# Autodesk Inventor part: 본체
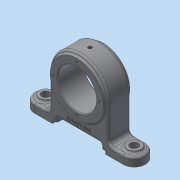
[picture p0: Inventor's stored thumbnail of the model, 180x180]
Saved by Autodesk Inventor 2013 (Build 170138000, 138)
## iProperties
Created: 2019-05
Part Number: 본체
Material: 일반
Document SubType Name: Modeling
Designer: dgall
Density: 1 g/cm^3
Author: dgall
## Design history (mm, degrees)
sketch "스케치1"
  geometry: L1 (0, 0)-(0, 60); C1 r 40 at (0, 60)
  constraints: 2 end point, 1 centre point, 1 coincident, 1 vertical
  dimensions: "d0" = 60 distance of L1.start L1.end; "d1" = 80 diameter of C1
extrude "돌출1" new body sketch "스케치1" stored distance "d2" = 30; taper "d3" = 0 deg
sketch "스케치2"
  geometry: L1 (0, -40)-(60, -40); L2 (0, 40)-(60, 40); L3 (60, 40)-(60, -40); L4 (60, 0)-(60, 75); L5 (60, 75)-(48, 75); L6 (48, 75)-(48, 40); L7 (60, 0)-(60, -75); L8 (60, -75)-(48, -75); L9 (48, -75)-(48, -40); A1 r 40 centre (0, 0) between (0, -40) and (0, 40) reference
  constraints: 18 end point, 4 perpendicular, 2 parallel, 2 point on circle, 2 point on line, 2 tangent, 1 collinear, 1 horizontal
  dimensions: "d4" = 60 distance of L1.start L1.end; "d5" = 60 distance of L2.start L2.end; "d6" = 75 distance of L4.start L4.end; "d7" = 12 distance of L4.end L5.end; "d8" = 75 distance of L4.start L7.end; "d9" = 12 distance of L7.end L8.end
extrude "돌출2" join sketch "스케치2" distance "d10" = 30; taper "d11" = 0 deg
fillet "모깎기1" dims "d12" = 15
fillet "모깎기2" dims "d13" = 15
sketch "스케치3"
  geometry: C1 r 9 at (15, -20); A1 r 15 centre (15, -20) between (0, -20) and (30, -20) reference; 1 further point
  constraints: 1 centre point, 1 coincident
  dimensions: "d14" = 18 diameter of C1
extrude "돌출3" join sketch "스케치3" distance "d16" = 3; taper "d17" = 0 deg
sketch "스케치4"
  geometry: C1 r 9 at (15, 20); A1 r 15 centre (15, 20) between (30, 20) and (0, 20) reference; 1 further point
  constraints: 1 centre point, 1 coincident
  dimensions: "d18" = 18 diameter of C1
extrude "돌출4" join sketch "스케치4" distance "d20" = 3; taper "d21" = 0 deg
fillet "모깎기3" dims "d22" = 3
fillet "모깎기4" dims "d23" = 3
fillet "모깎기5" dims "d24" = 6
fillet "모깎기6" dims "d25" = 3
sketch "스케치5"
  geometry: C1 r 9 at (0, 0) reference; C2 r 9 at (0, 120) reference; 1 further point
hole "구멍1" sketch "스케치5" at (0, 0), (0, 120) diameter "d26" = 11; stored, may be unused: countersink angle "d30" = 90 deg, drill point angle "d32" = 0 deg; dims "d27" = 6, "d28" = 4, "d29" = 2, "d31" = 20
sketch "스케치6"
  geometry: L1 (0, -60)-(0, 60) reference; L2 (0, 0)-(0, -36); L3 (0, -36)-(-4, -36); L4 (0, 0)-(0, 36); L5 (0, 36)-(-4, 36); L6 (0, 0)-(-10, 0); L7 (-10, 0)-(-10, -30); L8 (-10, -30)-(-4, -30); L9 (-4, -30)-(-4, -36); L10 (-10, 0)-(-10, 30); L11 (-10, 30)-(-4, 30); L12 (-4, 30)-(-4, 36)
  constraints: 22 end point, 4 perpendicular, 3 parallel, 2 point on line
  dimensions: "d33" = 36 distance of L2.start L2.end; "d34" = 4 distance of L2.end L3.end; "d35" = 36 distance of L2.start L4.end; "d36" = 4 distance of L4.end L5.end; "d37" = 10 distance of L2.start L6.end; "d38" = 30 distance of L6.end L7.end; "d39" = 6 distance of L7.end L8.end; "d40" = 30 distance of L6.end L10.end; "d41" = 6 distance of L10.end L11.end
extrude "돌출5" cut sketch "스케치6" stored distance "d42" = 3; taper "d43" = 0 deg
fillet "모깎기7" dims "d44" = 3
fillet "모깎기8" dims "d45" = 3
node "작업 평면1"
sketch "스케치7"
  geometry: L1 (-4, -33)-(-7, -33) reference; L2 (-4, -33)-(-4, -36) reference; L3 (-4, -36)-(0, -36) reference; L4 (0, -36)-(0, -60) reference; L5 (-9, -60)-(0, -60) reference; L6 (-9, -46)-(-9, -60) reference; L7 (-60, -37)-(-18, -37) reference; L8 (-18, 37)-(-60, 37) reference; L9 (-9, 60)-(-9, 46) reference; L10 (0, 60)-(-9, 60) reference; L11 (0, 60)-(0, 36) reference; L12 (0, 36)-(-4, 36) reference; L13 (-4, 36)-(-4, 33) reference; L14 (-7, 33)-(-4, 33) reference; L15 (-13, -27)-(-13, 27) reference; L16 (-18, 37)-(-60, 37) reference; L17 (-18, -40)-(-60, -40) reference; C1 r 36 at (-60, 0); A1 r 9 centre (-18, -46) between (-9, -46) and (-9.719, -42.474) reference; A2 r 37 centre (-60, 0) between (-60, 37) and (-60, -37) reference; A3 r 9 centre (-18, 46) between (-9.719, 42.474) and (-9, 46) reference; A4 r 6 centre (-7, 27) between (-7, 33) and (-13, 27) reference; A5 r 6 centre (-7, -27) between (-13, -27) and (-7, -33) reference; A6 r 40 centre (-60, 0) between (-60, 40) and (-60, -40) reference; 1 further point
  constraints: 1 centre point, 1 coincident, 2 other
  dimensions: "d46" = 72 diameter of C1
extrude "돌출6" join sketch "스케치7" stored distance "d48" = 36; taper "d49" = 0 deg
fillet "모깎기9" dims "d50" = 3
sketch "스케치8"
  geometry: C1 r 26 at (-60, 0); A1 r 36 centre (-60, 0) between (-48.62, 34.154) and (-48.62, -34.154) reference; 1 further point
  constraints: 1 centre point, 1 coincident
  dimensions: "d51" = 52 diameter of C1
extrude "돌출7" cut sketch "스케치8" stored distance "d53" = 36; taper "d54" = 0 deg
chamfer "모따기1" distance "d55" = 1; stored, may be unused: second distance "d56" = 2, angle "d57" = 45 deg
sketch "스케치9" dims "d58" = 62
  geometry: L1 (-60, 0)-(-29, 0); C1 r 27 at (-60, 0) reference; 1 further point
  constraints: 2 end point, 1 coincident, 1 horizontal, 1 horizontal alignment, 2 other
hole "구멍2" sketch "스케치9" at (-29, 0) diameter "d60" = 3.242; stored, may be unused: countersink angle "d64" = 90 deg, drill point angle "d66" = 118 deg; dims "d61" = 6, "d62" = 4, "d63" = 2, "d65" = 8
node "작업 평면2"
sketch "스케치10"
  geometry: L1 (-12, -100)-(-12, -20) reference; L2 (-12, -100)-(12, -100) reference; L3 (12, -20)-(12, -100) reference; L4 (-12, -20)-(12, -20) reference; 1 further point
hole "구멍3" sketch "스케치10" at (0, -60) diameter "d71" = 4.917; stored, may be unused: countersink angle "d75" = 82 deg, drill point angle "d77" = 118 deg; dims "d72" = 8, "d73" = 3.023, "d74" = 2, "d76" = 10
sketch "스케치11"
  geometry: C1 r 1 at (0, -60); 1 further point
  constraints: 1 centre point, 1 coincident
  dimensions: "d78" = 2 diameter of C1
extrude "돌출8" cut sketch "스케치11" stored distance "d80" = 36; taper "d81" = 0 deg
sketch "스케치12"
  geometry: L1 (-13, 27)-(-13, -27) reference; L2 (-10, -27)-(-10, 27) reference; 4 further points
  constraints: 1 coincident, 1 horizontal alignment, 1 midpoint, 1 other
  dimensions: "d83" = 7 distance from line of L2 point (-17, 0)
feature "엠보싱1" sketch "스케치12" dims "d0" = 60, "d1" = 80, "d12" = 15, "d84" = 0.5, "d85" = 0
node "솔리드1"
pattern_circular "원형 패턴1" dims angle "d68" = 360 deg
mirror "대칭1"
node "투영된 루프1"
node "투영된 루프2"
node "투영된 루프3"
